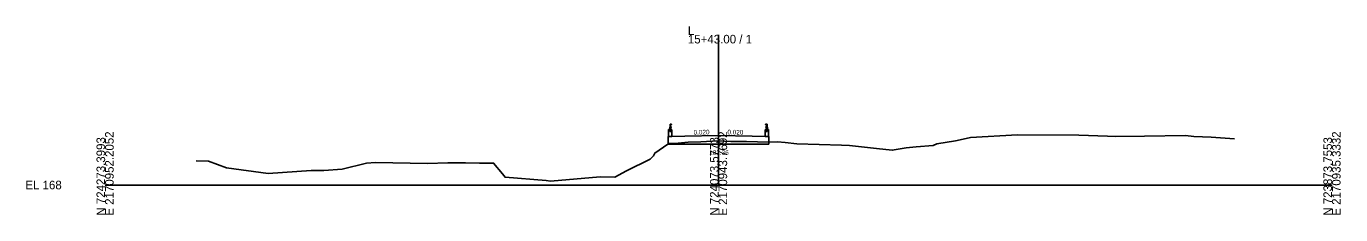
# Model space of a CAD drawing. Extents: x -26 to 2803, y -10 to 9553.
# Drawn here: x -25.7 to 402.8, y 6990.3 to 7051.8 of the extents above; entities that cross this region are included whole.
import ezdxf

# ---------------------------------------------------------------- set-up
doc = ezdxf.new("R2010")
doc.units = 0
for name, color, linetype in [('Exist Cross Section Cell', 7, 'Continuous'), ('Exist XS Center Line Elevation Label', 7, 'Continuous'), ('Exist XS Ground Line', 7, 'Continuous'), ('Prop XS Bridge', 7, 'Continuous'), ('Prop XS Dump Level', 7, 'Continuous'), ('Prop XS SE Text', 7, 'Continuous')]:
    doc.layers.add(name, color=color, linetype=linetype)

msp = doc.modelspace()

# ---------------------------------------------------------------- linework, layer by layer
at = {"layer": 'Exist Cross Section Cell'}
for p, q in [((200, 7000), (200, 7048.98)), ((0, 7000), (200, 7000)), ((200, 7000), (400, 7000))]:
    msp.add_line(p, q, dxfattribs=at)
at = {"layer": 'Exist XS Ground Line'}
msp.add_lwpolyline([(29.67, 7007.92), (33.7, 7007.78), (39.55, 7005.65), (53.15, 7003.78), (67.17, 7004.73), (71.32, 7004.77), (77.27, 7005.18), (85.26, 7007.16), (88.18, 7007.39), (105.11, 7007.01), (111.75, 7007.19), (117.46, 7007.2), (122.08, 7007.15), (126.66, 7007.14), (129.61, 7003.7), (130.42, 7002.51), (143.84, 7001.45), (145.22, 7001.21), (161.38, 7002.65), (166.24, 7002.52), (170.04, 7004.66), (177.66, 7008.43), (178.84, 7009.54), (179.24, 7010.41), (183.49, 7013.32), (183.92, 7013.49), (185.03, 7013.5), (185.65, 7013.56), (186.82, 7013.65), (190.07, 7013.95), (194.2, 7014.12), (199.84, 7014.36), (203.96, 7014.23), (209.06, 7014.14), (216.3, 7014.02), (219.22, 7014.05), (221.76, 7013.82), (225.53, 7013.44), (240.12, 7012.95), (242.71, 7012.87), (251.55, 7011.9), (256.64, 7011.34), (261.18, 7012.12), (264.4, 7012.45), (269.99, 7012.94), (271.19, 7013.42), (277.21, 7014.37), (280.72, 7015.14), (282.12, 7015.47), (297.44, 7016.33), (317.41, 7016.31), (326.82, 7015.88), (329.32, 7015.87), (338.83, 7015.93), (352.25, 7016.18), (354.97, 7015.83), (360.65, 7015.64), (368.23, 7015.1)], dxfattribs=at)
at = {"layer": 'Prop XS Bridge'}
for p, q in [((184.19, 7019.86), (184.07, 7018.14)), ((184.19, 7019.86), (184.3, 7019.9)), ((184.19, 7018.11), (184.19, 7019.86)), ((184.37, 7019.9), (184.3, 7019.9)), ((184.3, 7018.11), (184.3, 7019.9)), ((184.37, 7018.11), (184.37, 7019.9)), ((184.43, 7019.87), (184.43, 7019.77)), ((184.43, 7019.67), (184.43, 7019.77)), ((215.57, 7019.87), (215.57, 7019.77)), ((215.57, 7019.67), (215.57, 7019.77)), ((215.63, 7019.9), (215.7, 7019.9)), ((215.63, 7018.11), (215.63, 7019.9)), ((215.81, 7019.86), (215.7, 7019.9)), ((215.7, 7018.11), (215.7, 7019.9)), ((215.81, 7018.11), (215.81, 7019.86)), ((215.81, 7019.86), (215.93, 7018.14)), ((183.57, 7015.75), (183.62, 7015.8)), ((183.57, 7015.75), (183.57, 7013.29)), ((183.7, 7015.8), (183.62, 7015.8)), ((183.69, 7018.02), (183.73, 7018.07)), ((183.69, 7018.02), (183.69, 7015.8)), ((184.75, 7015.8), (183.7, 7015.8)), ((184.7, 7018.07), (183.73, 7018.07)), ((184.07, 7018.16), (184.07, 7018.19)), ((184.07, 7018.11), (184.07, 7018.14)), ((184.2, 7018.04), (184.11, 7018.04)), ((184.2, 7018.03), (184.11, 7018.03)), ((184.15, 7017.99), (184.11, 7017.99)), ((184.15, 7017.98), (184.11, 7017.98)), ((184.15, 7017.95), (184.11, 7017.95)), ((184.15, 7017.94), (184.11, 7017.94)), ((184.15, 7017.91), (184.11, 7017.91)), ((184.15, 7017.9), (184.11, 7017.9)), ((184.15, 7017.87), (184.11, 7017.87)), ((184.15, 7017.86), (184.11, 7017.86)), ((184.15, 7018.02), (184.13, 7018.02)), ((184.15, 7018.01), (184.13, 7018.01)), ((184.15, 7017.97), (184.13, 7017.97)), ((184.15, 7017.96), (184.13, 7017.96)), ((184.15, 7017.93), (184.13, 7017.93)), ((184.15, 7017.92), (184.13, 7017.92)), ((184.15, 7017.89), (184.13, 7017.89)), ((184.15, 7017.88), (184.13, 7017.88)), ((184.18, 7018.18), (184.14, 7018.18)), ((184.14, 7018.18), (184.14, 7018.15)), ((184.14, 7018.03), (184.14, 7018.11)), ((184.16, 7018.02), (184.15, 7018.02)), ((184.15, 7018.02), (184.15, 7017.51)), ((184.18, 7018.02), (184.16, 7018.02)), ((184.16, 7018.02), (184.16, 7017.51)), ((184.18, 7018.01), (184.16, 7018.01)), ((184.2, 7017.99), (184.16, 7017.99)), ((184.2, 7017.98), (184.16, 7017.98)), ((184.18, 7017.97), (184.16, 7017.97)), ((184.18, 7017.96), (184.16, 7017.96)), ((184.2, 7017.95), (184.16, 7017.95)), ((184.2, 7017.94), (184.16, 7017.94)), ((184.18, 7017.93), (184.16, 7017.93)), ((184.18, 7017.92), (184.16, 7017.92)), ((184.2, 7017.91), (184.16, 7017.91)), ((184.2, 7017.9), (184.16, 7017.9)), ((184.18, 7017.89), (184.16, 7017.89)), ((184.18, 7017.88), (184.16, 7017.88)), ((184.2, 7017.87), (184.16, 7017.87)), ((184.2, 7017.86), (184.16, 7017.86)), ((184.18, 7018.15), (184.18, 7018.18)), ((184.18, 7018.03), (184.18, 7018.11)), ((184.19, 7019.04), (184.19, 7019.04)), ((184.43, 7017.46), (184.21, 7017.46)), ((184.43, 7017.45), (184.21, 7017.45)), ((184.43, 7018.93), (184.43, 7018.83)), ((184.43, 7018.73), (184.43, 7018.83)), ((184.53, 7018.04), (184.44, 7018.04)), ((184.53, 7018.03), (184.44, 7018.03)), ((184.48, 7017.99), (184.44, 7017.99)), ((184.48, 7017.98), (184.44, 7017.98)), ((184.48, 7017.95), (184.44, 7017.95)), ((184.48, 7017.94), (184.44, 7017.94)), ((184.48, 7017.91), (184.44, 7017.91)), ((184.48, 7017.9), (184.44, 7017.9)), ((184.48, 7017.87), (184.44, 7017.87)), ((184.48, 7017.86), (184.44, 7017.86)), ((184.48, 7018.02), (184.46, 7018.02)), ((184.48, 7018.01), (184.46, 7018.01)), ((184.48, 7017.97), (184.46, 7017.97)), ((184.48, 7017.96), (184.46, 7017.96)), ((184.48, 7017.93), (184.46, 7017.93)), ((184.48, 7017.92), (184.46, 7017.92)), ((184.48, 7017.89), (184.46, 7017.89)), ((184.48, 7017.88), (184.46, 7017.88)), ((184.51, 7018.19), (184.47, 7018.19)), ((184.47, 7018.19), (184.47, 7018.16)), ((184.47, 7018.04), (184.47, 7018.12)), ((184.49, 7018.02), (184.48, 7018.02)), ((184.48, 7018.02), (184.48, 7017.51)), ((184.51, 7018.02), (184.49, 7018.02)), ((184.49, 7018.02), (184.49, 7017.51)), ((184.51, 7018.01), (184.49, 7018.01)), ((184.53, 7017.99), (184.49, 7017.99)), ((184.53, 7017.98), (184.49, 7017.98)), ((184.51, 7017.97), (184.49, 7017.97)), ((184.51, 7017.96), (184.49, 7017.96)), ((184.53, 7017.95), (184.49, 7017.95)), ((184.53, 7017.94), (184.49, 7017.94)), ((184.51, 7017.93), (184.49, 7017.93)), ((184.51, 7017.92), (184.49, 7017.92)), ((184.53, 7017.91), (184.49, 7017.91)), ((184.53, 7017.9), (184.49, 7017.9)), ((184.51, 7017.89), (184.49, 7017.89)), ((184.51, 7017.88), (184.49, 7017.88)), ((184.53, 7017.87), (184.49, 7017.87)), ((184.53, 7017.86), (184.49, 7017.86)), ((184.51, 7018.16), (184.51, 7018.19)), ((184.51, 7018.04), (184.51, 7018.12)), ((184.7, 7018.07), (184.75, 7018.02)), ((184.75, 7018.02), (184.75, 7015.8)), ((189, 7015.88), (184.75, 7015.8)), ((189, 7015.88), (200, 7016.1)), ((200, 7016.1), (211, 7015.88)), ((211, 7015.88), (215.25, 7015.8)), ((215.25, 7018.02), (215.3, 7018.07)), ((215.25, 7018.02), (215.25, 7015.8)), ((215.25, 7015.8), (216.3, 7015.8)), ((215.3, 7018.07), (216.27, 7018.07)), ((215.47, 7018.04), (215.56, 7018.04)), ((215.47, 7018.03), (215.56, 7018.03)), ((215.47, 7017.99), (215.51, 7017.99)), ((215.47, 7017.98), (215.51, 7017.98)), ((215.47, 7017.95), (215.51, 7017.95)), ((215.47, 7017.94), (215.51, 7017.94)), ((215.47, 7017.91), (215.51, 7017.91)), ((215.47, 7017.9), (215.51, 7017.9)), ((215.47, 7017.87), (215.51, 7017.87)), ((215.47, 7017.86), (215.51, 7017.86)), ((215.49, 7018.16), (215.49, 7018.19)), ((215.49, 7018.19), (215.53, 7018.19)), ((215.49, 7018.04), (215.49, 7018.12)), ((215.49, 7018.02), (215.51, 7018.02)), ((215.49, 7018.01), (215.51, 7018.01)), ((215.49, 7017.97), (215.51, 7017.97)), ((215.49, 7017.96), (215.51, 7017.96)), ((215.49, 7017.93), (215.51, 7017.93)), ((215.49, 7017.92), (215.51, 7017.92)), ((215.49, 7017.89), (215.51, 7017.89)), ((215.49, 7017.88), (215.51, 7017.88)), ((215.51, 7018.02), (215.52, 7018.02)), ((215.51, 7018.02), (215.51, 7017.51)), ((215.52, 7018.02), (215.54, 7018.02)), ((215.52, 7018.02), (215.52, 7017.51)), ((215.52, 7018.01), (215.54, 7018.01)), ((215.52, 7017.99), (215.56, 7017.99)), ((215.52, 7017.98), (215.56, 7017.98)), ((215.52, 7017.97), (215.54, 7017.97)), ((215.52, 7017.96), (215.54, 7017.96)), ((215.52, 7017.95), (215.56, 7017.95)), ((215.52, 7017.94), (215.56, 7017.94)), ((215.52, 7017.93), (215.54, 7017.93)), ((215.52, 7017.92), (215.54, 7017.92)), ((215.52, 7017.91), (215.56, 7017.91)), ((215.52, 7017.9), (215.56, 7017.9)), ((215.52, 7017.89), (215.54, 7017.89)), ((215.52, 7017.88), (215.54, 7017.88)), ((215.52, 7017.87), (215.56, 7017.87)), ((215.52, 7017.86), (215.56, 7017.86)), ((215.53, 7018.19), (215.53, 7018.16)), ((215.53, 7018.04), (215.53, 7018.12)), ((215.57, 7018.93), (215.57, 7018.83)), ((215.57, 7018.73), (215.57, 7018.83)), ((215.57, 7017.46), (215.79, 7017.46)), ((215.57, 7017.45), (215.79, 7017.45)), ((215.8, 7018.04), (215.89, 7018.04)), ((215.8, 7018.03), (215.89, 7018.03)), ((215.8, 7017.99), (215.84, 7017.99)), ((215.8, 7017.98), (215.84, 7017.98)), ((215.8, 7017.95), (215.84, 7017.95)), ((215.8, 7017.94), (215.84, 7017.94)), ((215.8, 7017.91), (215.84, 7017.91)), ((215.8, 7017.9), (215.84, 7017.9)), ((215.8, 7017.87), (215.84, 7017.87)), ((215.8, 7017.86), (215.84, 7017.86)), ((215.81, 7019.04), (215.81, 7019.04)), ((215.82, 7018.15), (215.82, 7018.18)), ((215.82, 7018.18), (215.86, 7018.18)), ((215.82, 7018.03), (215.82, 7018.11)), ((215.82, 7018.02), (215.84, 7018.02)), ((215.82, 7018.01), (215.84, 7018.01)), ((215.82, 7017.97), (215.84, 7017.97)), ((215.82, 7017.96), (215.84, 7017.96)), ((215.82, 7017.93), (215.84, 7017.93)), ((215.82, 7017.92), (215.84, 7017.92)), ((215.82, 7017.89), (215.84, 7017.89)), ((215.82, 7017.88), (215.84, 7017.88)), ((215.84, 7018.02), (215.85, 7018.02)), ((215.84, 7018.02), (215.84, 7017.51)), ((215.85, 7018.02), (215.87, 7018.02)), ((215.85, 7018.02), (215.85, 7017.51)), ((215.85, 7018.01), (215.87, 7018.01)), ((215.85, 7017.99), (215.89, 7017.99)), ((215.85, 7017.98), (215.89, 7017.98)), ((215.85, 7017.97), (215.87, 7017.97)), ((215.85, 7017.96), (215.87, 7017.96)), ((215.85, 7017.95), (215.89, 7017.95)), ((215.85, 7017.94), (215.89, 7017.94)), ((215.85, 7017.93), (215.87, 7017.93)), ((215.85, 7017.92), (215.87, 7017.92)), ((215.85, 7017.91), (215.89, 7017.91)), ((215.85, 7017.9), (215.89, 7017.9)), ((215.85, 7017.89), (215.87, 7017.89)), ((215.85, 7017.88), (215.87, 7017.88)), ((215.85, 7017.87), (215.89, 7017.87)), ((215.85, 7017.86), (215.89, 7017.86)), ((215.86, 7018.18), (215.86, 7018.15)), ((215.86, 7018.03), (215.86, 7018.11)), ((215.93, 7018.16), (215.93, 7018.19)), ((215.93, 7018.11), (215.93, 7018.14)), ((216.27, 7018.07), (216.31, 7018.02)), ((216.3, 7015.8), (216.38, 7015.8)), ((216.31, 7018.02), (216.31, 7015.8)), ((216.43, 7015.75), (216.38, 7015.8)), ((216.43, 7015.75), (216.43, 7013.29)), ((216.43, 7013.29), (183.57, 7013.29))]:
    msp.add_line(p, q, dxfattribs=at)
for points in [[(184.37, 7019.65), (184.37, 7019.69), (184.39, 7019.69), (184.39, 7019.68), (184.39, 7019.68), (184.39, 7019.66), (184.42, 7019.66), (184.42, 7019.69), (184.42, 7019.77), (184.42, 7019.84), (184.42, 7019.87), (184.39, 7019.87), (184.39, 7019.85), (184.39, 7019.85), (184.39, 7019.85), (184.37, 7019.85), (184.37, 7019.89)], [(215.63, 7019.65), (215.63, 7019.69), (215.61, 7019.69), (215.61, 7019.68), (215.61, 7019.68), (215.61, 7019.66), (215.58, 7019.66), (215.58, 7019.69), (215.58, 7019.77), (215.58, 7019.84), (215.58, 7019.87), (215.61, 7019.87), (215.61, 7019.85), (215.61, 7019.85), (215.61, 7019.85), (215.63, 7019.85), (215.63, 7019.89)], [(184.55, 7018.07), (184.55, 7018.12), (184.39, 7018.12), (184.39, 7018.48), (184.37, 7018.48), (184.37, 7018.11), (184.07, 7018.11), (184.07, 7018.13), (184.07, 7018.13), (184.07, 7018.07), (184.21, 7018.07), (184.21, 7018.1), (184.35, 7018.1), (184.35, 7018.07), (184.55, 7018.07)], [(184.11, 7018.04), (184.11, 7018.03), (184.13, 7018.02), (184.13, 7018.01), (184.11, 7017.99), (184.11, 7017.98), (184.13, 7017.97), (184.13, 7017.96), (184.11, 7017.95), (184.11, 7017.94), (184.13, 7017.93), (184.13, 7017.92), (184.11, 7017.91), (184.11, 7017.9), (184.13, 7017.89), (184.13, 7017.88), (184.11, 7017.87), (184.11, 7017.86)], [(184.2, 7018.11), (184.2, 7018.11), (184.16, 7018.11), (184.12, 7018.11), (184.12, 7018.11)], [(184.19, 7018.11), (184.19, 7018.14), (184.18, 7018.15), (184.13, 7018.15), (184.13, 7018.14), (184.13, 7018.11), (184.19, 7018.11), (184.17, 7018.11), (184.17, 7018.14), (184.17, 7018.15), (184.17, 7018.14), (184.16, 7018.15), (184.15, 7018.15), (184.15, 7018.14), (184.15, 7018.11), (184.15, 7018.14), (184.14, 7018.15)], [(184.2, 7018.04), (184.2, 7018.03), (184.18, 7018.02), (184.18, 7018.01), (184.2, 7017.99), (184.2, 7017.98), (184.18, 7017.97), (184.18, 7017.96), (184.2, 7017.95), (184.2, 7017.94), (184.18, 7017.93), (184.18, 7017.92), (184.2, 7017.91), (184.2, 7017.9), (184.18, 7017.89), (184.18, 7017.88), (184.2, 7017.87), (184.2, 7017.86)], [(184.37, 7018.71), (184.37, 7018.75), (184.39, 7018.75), (184.39, 7018.75), (184.39, 7018.75), (184.39, 7018.73), (184.42, 7018.73), (184.42, 7018.76), (184.42, 7018.83), (184.42, 7018.91), (184.42, 7018.94), (184.39, 7018.94), (184.39, 7018.92), (184.39, 7018.92), (184.39, 7018.91), (184.37, 7018.91), (184.37, 7018.96)], [(184.44, 7018.04), (184.44, 7018.03), (184.46, 7018.02), (184.46, 7018.01), (184.44, 7017.99), (184.44, 7017.98), (184.46, 7017.97), (184.46, 7017.96), (184.44, 7017.95), (184.44, 7017.94), (184.46, 7017.93), (184.46, 7017.92), (184.44, 7017.91), (184.44, 7017.9), (184.46, 7017.89), (184.46, 7017.88), (184.44, 7017.87), (184.44, 7017.86)], [(184.53, 7018.12), (184.53, 7018.12), (184.49, 7018.12), (184.45, 7018.12), (184.45, 7018.12)], [(184.52, 7018.12), (184.52, 7018.15), (184.51, 7018.15), (184.46, 7018.15), (184.46, 7018.15), (184.46, 7018.12), (184.52, 7018.12), (184.5, 7018.12), (184.5, 7018.15), (184.5, 7018.15), (184.5, 7018.15), (184.49, 7018.15), (184.48, 7018.15), (184.48, 7018.15), (184.48, 7018.12), (184.48, 7018.15), (184.47, 7018.15)], [(184.53, 7018.04), (184.53, 7018.03), (184.51, 7018.02), (184.51, 7018.01), (184.53, 7017.99), (184.53, 7017.98), (184.51, 7017.97), (184.51, 7017.96), (184.53, 7017.95), (184.53, 7017.94), (184.51, 7017.93), (184.51, 7017.92), (184.53, 7017.91), (184.53, 7017.9), (184.51, 7017.89), (184.51, 7017.88), (184.53, 7017.87), (184.53, 7017.86)], [(215.45, 7018.07), (215.45, 7018.12), (215.61, 7018.12), (215.61, 7018.48), (215.63, 7018.48), (215.63, 7018.11), (215.93, 7018.11), (215.93, 7018.13), (215.93, 7018.13), (215.93, 7018.07), (215.79, 7018.07), (215.79, 7018.1), (215.65, 7018.1), (215.65, 7018.07), (215.45, 7018.07)], [(215.47, 7018.12), (215.47, 7018.12), (215.51, 7018.12), (215.55, 7018.12), (215.55, 7018.12)], [(215.47, 7018.04), (215.47, 7018.03), (215.49, 7018.02), (215.49, 7018.01), (215.47, 7017.99), (215.47, 7017.98), (215.49, 7017.97), (215.49, 7017.96), (215.47, 7017.95), (215.47, 7017.94), (215.49, 7017.93), (215.49, 7017.92), (215.47, 7017.91), (215.47, 7017.9), (215.49, 7017.89), (215.49, 7017.88), (215.47, 7017.87), (215.47, 7017.86)], [(215.48, 7018.12), (215.48, 7018.15), (215.49, 7018.15), (215.54, 7018.15), (215.54, 7018.15), (215.54, 7018.12), (215.48, 7018.12), (215.5, 7018.12), (215.5, 7018.15), (215.5, 7018.15), (215.5, 7018.15), (215.51, 7018.15), (215.52, 7018.15), (215.52, 7018.15), (215.52, 7018.12), (215.52, 7018.15), (215.53, 7018.15)], [(215.56, 7018.04), (215.56, 7018.03), (215.54, 7018.02), (215.54, 7018.01), (215.56, 7017.99), (215.56, 7017.98), (215.54, 7017.97), (215.54, 7017.96), (215.56, 7017.95), (215.56, 7017.94), (215.54, 7017.93), (215.54, 7017.92), (215.56, 7017.91), (215.56, 7017.9), (215.54, 7017.89), (215.54, 7017.88), (215.56, 7017.87), (215.56, 7017.86)], [(215.63, 7018.71), (215.63, 7018.75), (215.61, 7018.75), (215.61, 7018.75), (215.61, 7018.75), (215.61, 7018.73), (215.58, 7018.73), (215.58, 7018.76), (215.58, 7018.83), (215.58, 7018.91), (215.58, 7018.94), (215.61, 7018.94), (215.61, 7018.92), (215.61, 7018.92), (215.61, 7018.91), (215.63, 7018.91), (215.63, 7018.96)], [(215.8, 7018.11), (215.8, 7018.11), (215.84, 7018.11), (215.88, 7018.11), (215.88, 7018.11)], [(215.8, 7018.04), (215.8, 7018.03), (215.82, 7018.02), (215.82, 7018.01), (215.8, 7017.99), (215.8, 7017.98), (215.82, 7017.97), (215.82, 7017.96), (215.8, 7017.95), (215.8, 7017.94), (215.82, 7017.93), (215.82, 7017.92), (215.8, 7017.91), (215.8, 7017.9), (215.82, 7017.89), (215.82, 7017.88), (215.8, 7017.87), (215.8, 7017.86)], [(215.81, 7018.11), (215.81, 7018.14), (215.82, 7018.15), (215.87, 7018.15), (215.87, 7018.14), (215.87, 7018.11), (215.81, 7018.11), (215.83, 7018.11), (215.83, 7018.14), (215.83, 7018.15), (215.83, 7018.14), (215.84, 7018.15), (215.85, 7018.15), (215.85, 7018.14), (215.85, 7018.11), (215.85, 7018.14), (215.86, 7018.15)], [(215.89, 7018.04), (215.89, 7018.03), (215.87, 7018.02), (215.87, 7018.01), (215.89, 7017.99), (215.89, 7017.98), (215.87, 7017.97), (215.87, 7017.96), (215.89, 7017.95), (215.89, 7017.94), (215.87, 7017.93), (215.87, 7017.92), (215.89, 7017.91), (215.89, 7017.9), (215.87, 7017.89), (215.87, 7017.88), (215.89, 7017.87), (215.89, 7017.86)]]:
    msp.add_lwpolyline(points, dxfattribs=at)
for centre in [(184.12, 7017.88), (184.53, 7017.88), (215.47, 7017.88), (215.88, 7017.88)]:
    msp.add_circle(centre, 0.00793, dxfattribs=at)
for centre, radius, start, end in [((184.44, 7019.87), 0.00744, 90, 180), ((184.44, 7019.67), 0.00744, 180, 270), ((215.56, 7019.87), 0.00744, 0, 90), ((215.56, 7019.67), 0.00744, 270, 360), ((184.21, 7017.51), 0.0665, 180, 270), ((184.21, 7017.51), 0.0507, 180, 270), ((184.44, 7018.93), 0.00744, 90, 180), ((184.44, 7018.73), 0.00744, 180, 270), ((184.43, 7017.51), 0.0507, 270, 0), ((184.43, 7017.51), 0.0665, 270, 0), ((215.57, 7017.51), 0.0665, 180, 270), ((215.57, 7017.51), 0.0507, 180, 270), ((215.56, 7018.93), 0.00744, 0, 90), ((215.56, 7018.73), 0.00744, 270, 360), ((215.79, 7017.51), 0.0507, 270, 0), ((215.79, 7017.51), 0.0665, 270, 0)]:
    msp.add_arc(centre, radius, start, end, dxfattribs=at)
for centre, major_axis, ratio, start_param, end_param in [((184.37, 7019.77), (0.318, 0), 0.39036, 6.282787, 7.853967), ((184.37, 7019.77), (0.318, 0), 0.39036, 4.712404, 6.282787), ((184.44, 7019.77), (0.211, 0), 0.495501, 6.282718, 7.853881), ((184.44, 7019.77), (0.211, 0), 0.495501, 4.712489, 6.282718), ((215.63, 7019.77), (-0.318, 0), 0.39036, 4.712404, 6.283584), ((215.63, 7019.77), (-0.318, 0), 0.39036, 0.000398, 1.570782), ((215.56, 7019.77), (-0.211, 0), 0.495501, 4.712489, 6.283652), ((215.56, 7019.77), (-0.211, 0), 0.495501, 0.000467, 1.570696), ((184.37, 7018.83), (0.318, 0), 0.39036, 6.282787, 7.853967), ((184.37, 7018.83), (0.318, 0), 0.39036, 4.712404, 6.282787), ((184.44, 7018.83), (0.211, 0), 0.495501, 6.282718, 7.853881), ((184.44, 7018.83), (0.211, 0), 0.495501, 4.712489, 6.282718), ((215.63, 7018.83), (-0.318, 0), 0.39036, 4.712404, 6.283584), ((215.63, 7018.83), (-0.318, 0), 0.39036, 0.000398, 1.570782), ((215.56, 7018.83), (-0.211, 0), 0.495501, 4.712489, 6.283652), ((215.56, 7018.83), (-0.211, 0), 0.495501, 0.000467, 1.570696)]:
    msp.add_ellipse(centre, major_axis=major_axis, ratio=ratio, start_param=start_param, end_param=end_param, dxfattribs=at)
at = {"layer": 'Prop XS Dump Level'}
for p, q in [((189, 7015.88), (200, 7016.1)), ((200, 7016.1), (211, 7015.88))]:
    msp.add_line(p, q, dxfattribs=at)

# ---------------------------------------------------------------- texts
at = {"layer": 'Exist Cross Section Cell'}
for s, p in [('L', (190, 7048.98)), ('15+43.00 / 1', (190, 7046.18)), ('EL 168', (-26, 6998.6))]:
    msp.add_text(s, height=2.8, dxfattribs=at).set_placement(p)
for s, p in [('N 724273.3993', (0, 6990)), ('E 2170952.2052', (2.8, 6990)), ('N 724073.5773', (200, 6990)), ('E 2170943.7692', (202.8, 6990)), ('N 723873.7553', (400, 6990)), ('E 2170935.3332', (402.8, 6990))]:
    msp.add_text(s, height=2.8, rotation=90, dxfattribs=at).set_placement(p)
at = {"layer": 'Exist XS Center Line Elevation Label'}
msp.add_text('182.36', height=1.5, dxfattribs=at).set_placement((196.98, 7009.86))
at = {"layer": 'Prop XS SE Text'}
for rotation, p in [(1.1458, (191.88, 7016.44)), (358.8542, (202.88, 7016.54))]:
    msp.add_text('0.020', height=1.5, rotation=rotation, dxfattribs=at).set_placement(p)

doc.saveas('drawing.dxf')
